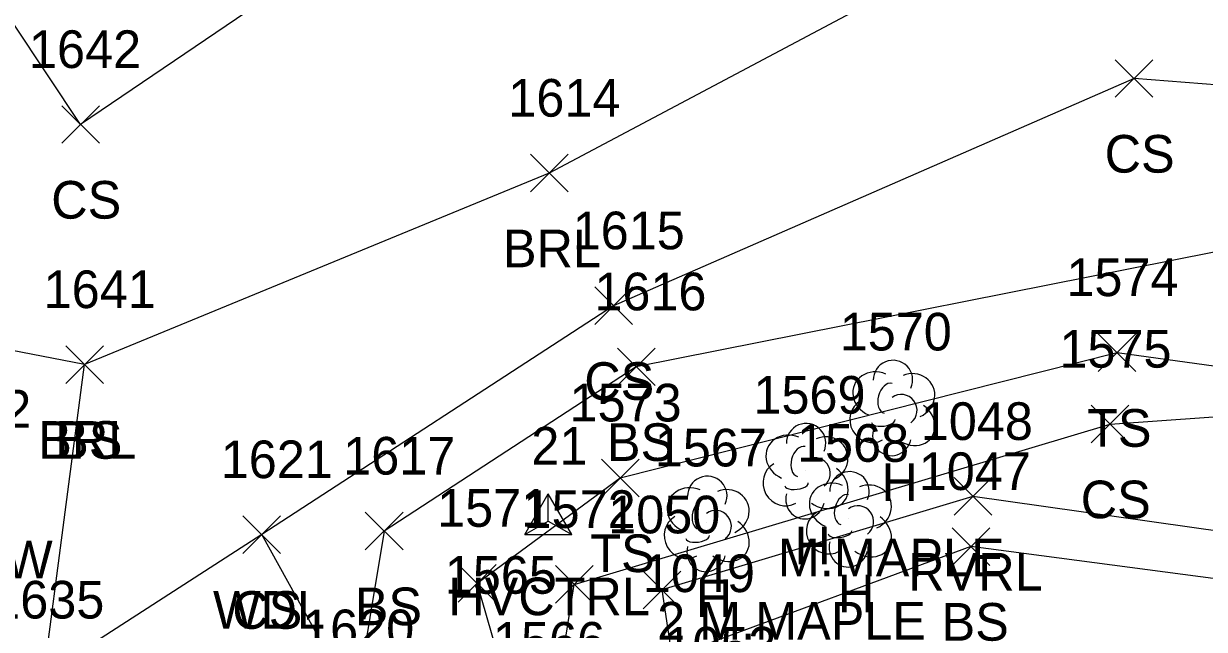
# Model space of a CAD drawing. Extents: x 1469310 to 1475157, y 493997 to 498873.
# Drawn here: x 1469560.4 to 1469623, y 498619.2 to 498651.4 of the extents above; entities that cross this region are included whole.
import ezdxf

# ---------------------------------------------------------------- set-up
doc = ezdxf.new("R2010")
doc.units = 0
for name, color, linetype in [('C_A', 7, 'Continuous'), ('C_I', 7, 'Continuous'), ('CPSM', 7, 'Continuous'), ('L_A', 7, 'Continuous'), ('L_C', 7, 'Continuous'), ('L_I', 7, 'Continuous'), ('L_TIC', 7, 'Continuous'), ('LABL', 7, 'Continuous'), ('LAWA', 7, 'Continuous'), ('LAWE', 7, 'Continuous'), ('LELB', 7, 'Continuous'), ('LTD', 7, 'Continuous')]:
    doc.layers.add(name, color=color, linetype=linetype)

msp = doc.modelspace()

# ---------------------------------------------------------------- linework, layer by layer
at = {"layer": 'CPSM'}
for p, q in [((1469586.969, 498624.242), (1469588.219, 498626.407)), ((1469589.469, 498624.242), (1469588.219, 498626.407)), ((1469588.22, 498624.963), (1469588.219, 498626.407)), ((1469586.969, 498624.242), (1469588.22, 498624.963)), ((1469588.22, 498624.963), (1469588.22, 498624.963)), ((1469588.22, 498624.963), (1469589.469, 498624.242)), ((1469586.969, 498624.242), (1469589.469, 498624.242))]:
    msp.add_line(p, q, dxfattribs=at)
at = {"layer": 'L_TIC'}
for points in [[(1469618.31, 498647.468), (1469620.31, 498649.468)], [(1469620.31, 498647.468), (1469618.31, 498649.468)], [(1469562.399, 498645.025), (1469564.399, 498647.025)], [(1469564.399, 498645.025), (1469562.399, 498647.025)], [(1469587.273, 498642.441), (1469589.273, 498644.441)], [(1469589.273, 498642.441), (1469587.273, 498644.441)], [(1469590.689, 498635.397), (1469592.689, 498637.397)], [(1469592.689, 498635.397), (1469590.689, 498637.397)], [(1469617.412, 498632.909), (1469619.412, 498634.909)], [(1469619.412, 498632.909), (1469617.412, 498634.909)], [(1469562.61, 498632.273), (1469564.61, 498634.273)], [(1469564.61, 498632.273), (1469562.61, 498634.273)], [(1469562.61, 498632.273), (1469564.61, 498634.273)], [(1469564.61, 498632.273), (1469562.61, 498634.273)], [(1469591.894, 498632.155), (1469593.894, 498634.155)], [(1469593.894, 498632.155), (1469591.894, 498634.155)], [(1469617.042, 498629.111), (1469619.042, 498631.111)], [(1469619.042, 498629.111), (1469617.042, 498631.111)], [(1469591.042, 498626.254), (1469593.042, 498628.254)], [(1469593.042, 498626.254), (1469591.042, 498628.254)], [(1469609.764, 498625.27), (1469611.764, 498627.27)], [(1469611.764, 498625.27), (1469609.764, 498627.27)], [(1469572.01, 498623.242), (1469574.01, 498625.242)], [(1469574.01, 498623.242), (1469572.01, 498625.242)], [(1469572.01, 498623.242), (1469574.01, 498625.242)], [(1469574.01, 498623.242), (1469572.01, 498625.242)], [(1469578.511, 498623.432), (1469580.511, 498625.432)], [(1469580.511, 498623.432), (1469578.511, 498625.432)], [(1469609.656, 498622.611), (1469611.656, 498624.611)], [(1469611.656, 498622.611), (1469609.656, 498624.611)], [(1469583.447, 498620.658), (1469585.447, 498622.658)], [(1469585.447, 498620.658), (1469583.447, 498622.658)], [(1469588.604, 498620.597), (1469590.604, 498622.597)], [(1469590.604, 498620.597), (1469588.604, 498622.597)], [(1469593.257, 498620.311), (1469595.257, 498622.311)], [(1469595.257, 498620.311), (1469593.257, 498622.311)]]:
    msp.add_lwpolyline(points, dxfattribs=at)
at = {"layer": 'LABL'}
msp.add_lwpolyline([(1469804.951, 498565.122), (1469764.815, 498561.657), (1469749.085, 498576.217), (1469733.116, 498600.55), (1469716.502, 498617.668), (1469685.262, 498643.727), (1469661.907, 498654.328), (1469615.65, 498657.999), (1469588.273, 498643.441), (1469563.61, 498633.273)], dxfattribs=at)
at = {"layer": 'LAWA'}
for points in [[(1469561.449, 498616.788), (1469563.61, 498633.273)], [(1469612.833, 498546.464), (1469619.738, 498548.83), (1469612.977, 498555.124), (1469604.978, 498569.723), (1469601.64, 498578.733), (1469597.441, 498587.632), (1469591.889, 498597.878), (1469577.982, 498615.263), (1469573.01, 498624.242), (1469561.449, 498616.788)]]:
    msp.add_lwpolyline(points, dxfattribs=at)
at = {"layer": 'LAWE'}
msp.add_lwpolyline([(1469773.599, 498538.143), (1469743.152, 498547.619), (1469721.093, 498561.124), (1469693.491, 498583.351), (1469669.748, 498607.461), (1469645.136, 498621.402), (1469610.764, 498626.27), (1469594.257, 498621.311), (1469595.404, 498613.659), (1469596.705, 498614.177)], dxfattribs=at)
at = {"layer": 'LELB'}
for points in [[(1469689.874, 498657.87), (1469664.198, 498669.39), (1469609.729, 498671.933), (1469582.144, 498658.759), (1469563.399, 498646.025), (1469554.478, 498659.448), (1469546.055, 498676.671), (1469525.383, 498698.234), (1469503.854, 498725.442), (1469472.452, 498754.543), (1469455.127, 498777.294), (1469419.867, 498802.33), (1469400.99, 498819.039), (1469383.055, 498844.763)], [(1469749.085, 498576.217), (1469720.606, 498588.908), (1469694.201, 498602.154), (1469680.981, 498626.156), (1469659.92, 498645.282), (1469619.31, 498648.468), (1469591.689, 498636.397), (1469573.01, 498624.242)], [(1469687.639, 498598.943), (1469677.953, 498621.464), (1469659.583, 498639.402), (1469625.704, 498639.67), (1469592.894, 498633.155), (1469579.511, 498624.432), (1469577.982, 498615.263)], [(1469563.61, 498633.273), (1469550.256, 498635.871)], [(1469600.588, 498604.32), (1469587.662, 498609.367), (1469585.469, 498618.104), (1469584.447, 498621.658), (1469592.042, 498627.254), (1469618.412, 498633.909), (1469636.49, 498631.421), (1469646.843, 498626.766), (1469675.4, 498609.126), (1469687.639, 498598.943), (1469700.03, 498583.669), (1469721.266, 498569.857), (1469752.353, 498551.496), (1469778.45, 498547.84), (1469808.958, 498549.067)], [(1469625.46, 498586.142), (1469619.296, 498585.147), (1469606.231, 498585.955), (1469602.337, 498593.71), (1469604.707, 498595.752), (1469602.628, 498599.074), (1469600.588, 498604.32), (1469596.556, 498609.811), (1469594.143, 498610.889), (1469587.662, 498609.367), (1469589.604, 498621.597), (1469618.042, 498630.111), (1469636.49, 498631.421)], [(1469772.295, 498536.699), (1469742.731, 498545.987), (1469719.144, 498559.139), (1469691.198, 498582.668), (1469667.675, 498605.387), (1469646.545, 498618.868), (1469610.656, 498623.611), (1469596.02, 498618.19), (1469597.153, 498614.345), (1469602.07, 498605.375)]]:
    msp.add_lwpolyline(points, dxfattribs=at)
at = {"layer": 'LTD'}
for p, q in [((1469606.469, 498631.023), (1469606.469, 498631.023)), ((1469606.469, 498631.023), (1469606.469, 498631.023)), ((1469601.857, 498627.667), (1469601.857, 498627.667)), ((1469601.857, 498627.667), (1469601.857, 498627.667)), ((1469596.614, 498624.864), (1469596.614, 498624.864)), ((1469596.614, 498624.864), (1469596.614, 498624.864)), ((1469604.163, 498625.11), (1469604.163, 498625.11)), ((1469604.163, 498625.11), (1469604.163, 498625.11))]:
    msp.add_line(p, q, dxfattribs=at)
for centre in [(1469606.515, 498632.457), (1469601.904, 498629.101), (1469604.21, 498626.544), (1469596.661, 498626.298)]:
    msp.add_arc(centre, 1.047, 335.52715, 180.95627, dxfattribs=at)
for centre, major_axis, ratio, start_param, end_param in [((1469605.677, 498631.689), (1.21, -0.512), 0.895232, 1.570796, 4.712389), ((1469607.51, 498631.606), (-1.141, -0.483), 0.949671, 1.570796, 4.712389), ((1469606.26, 498631.481), (-0.208, -0.792), 0.645439, 3.141593, 6.283185), ((1469606.969, 498630.856), (-0.5, 0.667), 0.989748, 3.141593, 6.283185), ((1469605.385, 498630.314), (0.584, -1.042), 0.959034, 3.141593, 6.283185), ((1469607.469, 498630.19), (-1.09, 0.792), 0.841452, 1.570796, 4.712389), ((1469606.01, 498630.273), (-0.625, -0.083), 0.423636, 0, 3.141593), ((1469601.065, 498628.333), (1.21, -0.512), 0.895232, 1.570796, 4.712389), ((1469602.899, 498628.25), (-1.141, -0.483), 0.949671, 1.570796, 4.712389), ((1469606.469, 498629.523), (0.265, 1.061), 0.942809, 1.570796, 4.712389), ((1469601.649, 498628.125), (-0.208, -0.792), 0.645439, 3.141593, 6.283185), ((1469600.774, 498626.958), (0.584, -1.042), 0.959034, 3.141593, 6.283185), ((1469602.357, 498627.5), (-0.5, 0.667), 0.989748, 3.141593, 6.283185), ((1469602.857, 498626.834), (-1.09, 0.792), 0.841452, 1.570796, 4.712389), ((1469595.822, 498625.531), (1.21, -0.512), 0.895232, 1.570796, 4.712389), ((1469597.656, 498625.448), (-1.141, -0.483), 0.949671, 1.570796, 4.712389), ((1469601.399, 498626.917), (-0.625, -0.083), 0.423636, 0, 3.141593), ((1469603.371, 498625.776), (1.21, -0.512), 0.895232, 1.570796, 4.712389), ((1469605.205, 498625.693), (-1.141, -0.483), 0.949671, 1.570796, 4.712389), ((1469596.406, 498625.322), (-0.208, -0.792), 0.645439, 3.141593, 6.283185), ((1469601.857, 498626.167), (0.265, 1.061), 0.942809, 1.570796, 4.712389), ((1469603.955, 498625.568), (-0.208, -0.792), 0.645439, 3.141593, 6.283185), ((1469597.114, 498624.698), (-0.5, 0.667), 0.989748, 3.141593, 6.283185), ((1469604.663, 498624.943), (-0.5, 0.667), 0.989748, 3.141593, 6.283185), ((1469595.531, 498624.156), (0.584, -1.042), 0.959034, 3.141593, 6.283185), ((1469597.614, 498624.031), (-1.09, 0.792), 0.841452, 1.570796, 4.712389), ((1469603.08, 498624.401), (0.584, -1.042), 0.959034, 3.141593, 6.283185), ((1469605.163, 498624.276), (-1.09, 0.792), 0.841452, 1.570796, 4.712389), ((1469603.705, 498624.36), (-0.625, -0.083), 0.423636, 0, 3.141593), ((1469596.614, 498623.364), (0.265, 1.061), 0.942809, 1.570796, 4.712389), ((1469596.156, 498624.114), (-0.625, -0.083), 0.423636, 0, 3.141593), ((1469604.163, 498623.61), (0.265, 1.061), 0.942809, 1.570796, 4.712389)]:
    msp.add_ellipse(centre, major_axis=major_axis, ratio=ratio, start_param=start_param, end_param=end_param, dxfattribs=at)

# ---------------------------------------------------------------- texts
at = {"layer": 'C_A'}
msp.add_text('HVCTRL', height=2, dxfattribs=at).set_placement((1469582.913, 498619.963))
at = {"layer": 'C_I'}
msp.add_text('21', height=2, dxfattribs=at).set_placement((1469587.322, 498627.963))
at = {"layer": 'L_A'}
for s, p in [('CS', (1469617.751, 498643.468)), ('CS', (1469561.84, 498641.025)), ('BRL', (1469585.817, 498638.441)), ('CS', (1469590.13, 498631.397)), ('TS', (1469616.822, 498628.909)), ('BRL', (1469561.153, 498628.273)), ('BS', (1469562.051, 498628.273)), ('BS', (1469591.335, 498628.155)), ('H', (1469605.902, 498626.023)), ('CS', (1469616.482, 498625.111)), ('TS', (1469590.451, 498622.254)), ('H', (1469601.29, 498622.667)), ('FNBW', (1469554.043, 498621.919)), ('RVRL', (1469607.331, 498621.27)), ('H', (1469596.047, 498619.864)), ('H', (1469603.596, 498620.11)), ('WDL', (1469570.427, 498619.242)), ('CS', (1469571.451, 498619.242)), ('BS', (1469577.952, 498619.432)), ('BS', (1469609.097, 498618.611))]:
    msp.add_text(s, height=2, dxfattribs=at).set_placement(p)
at = {"layer": 'L_C'}
for s, p in [('M.MAPLE', (1469600.406, 498622.023)), ('2 M.MAPLE', (1469593.999, 498618.667))]:
    msp.add_text(s, height=2, dxfattribs=at).set_placement(p)
at = {"layer": 'L_I'}
for s, p in [('1642', (1469560.659, 498649.025)), ('1614', (1469586.1, 498646.441)), ('1615', (1469589.516, 498639.397)), ('1574', (1469615.72, 498636.909)), ('1641', (1469561.437, 498636.273)), ('1641', (1469561.437, 498636.273)), ('1616', (1469590.666, 498636.155)), ('1570', (1469603.689, 498634.023)), ('1575', (1469615.349, 498633.111)), ('1569', (1469599.109, 498630.667)), ('1652', (1469554.83, 498629.919)), ('1573', (1469589.349, 498630.254)), ('1048', (1469607.993, 498629.27)), ('1567', (1469593.874, 498627.864)), ('1568', (1469601.423, 498628.11)), ('1621', (1469570.837, 498627.242)), ('1621', (1469570.837, 498627.242)), ('1617', (1469577.338, 498627.432)), ('1047', (1469607.884, 498626.611)), ('1571', (1469582.321, 498624.658)), ('1572', (1469586.911, 498624.597)), ('1050', (1469591.399, 498624.311)), ('1565', (1469582.729, 498621.104)), ('1049', (1469593.241, 498621.19)), ('1635', (1469558.709, 498619.788)), ('1635', (1469558.709, 498619.788)), ('1620', (1469575.155, 498618.263)), ('1620', (1469575.155, 498618.263)), ('1566', (1469585.286, 498617.601)), ('1053', (1469594.382, 498617.345))]:
    msp.add_text(s, height=2, dxfattribs=at).set_placement(p)

doc.saveas('drawing.dxf')
